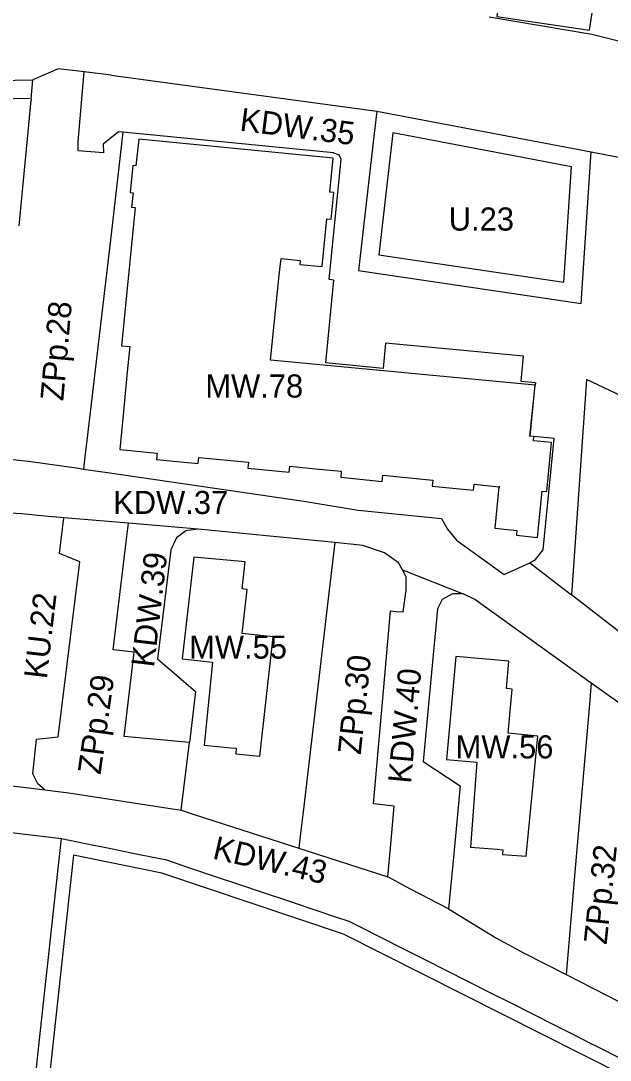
# Model space of a CAD drawing. Extents: x 7424434 to 7425898, y 5541432 to 5542659.
# Drawn here: x 7425392.8 to 7425520.4, y 5541625.5 to 5541850.5 of the extents above; entities that cross this region are included whole.
import ezdxf

# ---------------------------------------------------------------- set-up
doc = ezdxf.new("R2010")
doc.units = 0
for name, color, linetype in [('linie rozgraniczające', 7, 'Continuous'), ('nieprzekraczalne linie zabudowy', 7, 'Continuous'), ('obowiazujace linie zabudowy', 7, 'Continuous'), ('przeznaczenia terenów', 7, 'Continuous')]:
    doc.layers.add(name, color=color, linetype=linetype)

msp = doc.modelspace()

# ---------------------------------------------------------------- linework, layer by layer
at = {"layer": 'linie rozgraniczające'}
for p, q in [((7425516.46, 5541847.52), (7425494.23, 5541851.23)), ((7425522.8, 5541845.92), (7425516.46, 5541847.52)), ((7425345.98, 5541836.72), (7425395.46, 5541837.71)), ((7425395.07, 5541833.56), (7425395.46, 5541837.71)), ((7425405.25, 5541824.25), (7425406.57, 5541839.4)), ((7425412.43, 5541838.68), (7425406.57, 5541839.4)), ((7425412.43, 5541838.68), (7425469.86, 5541830.93)), ((7425394.55, 5541827.93), (7425395.05, 5541833.31)), ((7425395.07, 5541833.56), (7425395.05, 5541833.31)), ((7425469.86, 5541830.93), (7425469.3, 5541826.03)), ((7425392.52, 5541806.05), (7425394.55, 5541827.93)), ((7425413.98, 5541826.45), (7425410.7, 5541823.77)), ((7425414.93, 5541826.36), (7425412.37, 5541804.28)), ((7425414.93, 5541826.36), (7425413.98, 5541826.45)), ((7425460.55, 5541821.87), (7425414.93, 5541826.36)), ((7425469.3, 5541826.03), (7425465.91, 5541796.39)), ((7425405.25, 5541822.33), (7425405.25, 5541824.25)), ((7425410.7, 5541823.77), (7425410.72, 5541821.85)), ((7425410.72, 5541821.85), (7425405.25, 5541822.33)), ((7425460.55, 5541821.87), (7425461.74, 5541821.42)), ((7425462.17, 5541820.54), (7425461.74, 5541821.42)), ((7425514.1, 5541789.29), (7425516.28, 5541822.09)), ((7425459.55, 5541794.44), (7425462.17, 5541820.54)), ((7425412.37, 5541804.28), (7425406.96, 5541758.4)), ((7425460.6, 5541794.34), (7425459.55, 5541794.44)), ((7425465.91, 5541796.39), (7425514.1, 5541789.29)), ((7425458.83, 5541776.39), (7425460.6, 5541794.34)), ((7425471.8, 5541780.69), (7425471.28, 5541775.22)), ((7425501.67, 5541777.86), (7425471.8, 5541780.69)), ((7425501.15, 5541772.39), (7425501.67, 5541777.86)), ((7425471.28, 5541775.22), (7425458.83, 5541776.39)), ((7425504.2, 5541772.1), (7425501.15, 5541772.39)), ((7425504.2, 5541772.1), (7425504.16, 5541771.6)), ((7425515.3, 5541772.85), (7425512.02, 5541726.19)), ((7425528.15, 5541766.73), (7425515.3, 5541772.85)), ((7425503.03, 5541760.57), (7425504.16, 5541771.6)), ((7425503.86, 5541760.5), (7425503.03, 5541760.57)), ((7425508.27, 5541760.07), (7425503.86, 5541760.5)), ((7425505.9, 5541735.97), (7425508.27, 5541760.07)), ((7425406.7, 5541756.18), (7425406.38, 5541753.44)), ((7425406.96, 5541758.4), (7425406.7, 5541756.18)), ((7425385.12, 5541756.09), (7425394.51, 5541755.17)), ((7425394.51, 5541755.17), (7425405.3, 5541753.6)), ((7425405.3, 5541753.6), (7425406.38, 5541753.44)), ((7425406.38, 5541753.44), (7425411.59, 5541752.68)), ((7425411.59, 5541752.68), (7425454.13, 5541746.46)), ((7425454.13, 5541746.46), (7425455.86, 5541746.17)), ((7425455.86, 5541746.17), (7425465.85, 5541744.51)), ((7425393.08, 5541743.75), (7425383.22, 5541744.34)), ((7425398.02, 5541743.25), (7425393.08, 5541743.75)), ((7425402.12, 5541742.9), (7425398.02, 5541743.25)), ((7425401.2, 5541735.15), (7425402.12, 5541742.9)), ((7425416.15, 5541741.72), (7425402.12, 5541742.9)), ((7425465.85, 5541744.51), (7425483.92, 5541742.7)), ((7425483.92, 5541742.7), (7425485.22, 5541740.41)), ((7425415.73, 5541738.29), (7425416.15, 5541741.72)), ((7425431.23, 5541740.45), (7425416.15, 5541741.72)), ((7425431.23, 5541740.45), (7425428.57, 5541740.07)), ((7425460.83, 5541737.52), (7425431.23, 5541740.45)), ((7425412.81, 5541714.33), (7425415.73, 5541738.29)), ((7425426.51, 5541738.53), (7425425.31, 5541735.94)), ((7425428.57, 5541740.07), (7425426.51, 5541738.53)), ((7425485.22, 5541740.41), (7425487.12, 5541738.08)), ((7425425.31, 5541735.94), (7425422.87, 5541715.83)), ((7425460.83, 5541737.52), (7425459.61, 5541727.21)), ((7425466.87, 5541736.92), (7425460.83, 5541737.52)), ((7425471.57, 5541735.29), (7425466.87, 5541736.92)), ((7425487.12, 5541738.08), (7425497.43, 5541730.61)), ((7425504.24, 5541733.85), (7425505.9, 5541735.97)), ((7425405.59, 5541733.39), (7425401.2, 5541735.15)), ((7425474.6, 5541733.17), (7425471.57, 5541735.29)), ((7425503.03, 5541733.14), (7425504.24, 5541733.85)), ((7425400.94, 5541695.5), (7425405.59, 5541733.39)), ((7425475.44, 5541731.61), (7425474.6, 5541733.17)), ((7425475.44, 5541731.61), (7425488.61, 5541726.42)), ((7425476.25, 5541730.08), (7425475.44, 5541731.61)), ((7425497.43, 5541730.61), (7425503.03, 5541733.14)), ((7425503.03, 5541733.14), (7425512.02, 5541726.19)), ((7425476.24, 5541727.19), (7425476.25, 5541730.08)), ((7425459.61, 5541727.21), (7425453.93, 5541679.25)), ((7425475.58, 5541722.5), (7425476.24, 5541727.19)), ((7425484.03, 5541725.18), (7425483.04, 5541723.17)), ((7425486.3, 5541726.43), (7425484.03, 5541725.18)), ((7425488.61, 5541726.42), (7425486.3, 5541726.43)), ((7425491.07, 5541725.24), (7425488.61, 5541726.42)), ((7425516.3, 5541707.13), (7425491.07, 5541725.24)), ((7425538, 5541706.09), (7425512.02, 5541726.19)), ((7425471.62, 5541708.66), (7425472.87, 5541722.72)), ((7425472.87, 5541722.72), (7425474.05, 5541722.63)), ((7425474.05, 5541722.63), (7425475.58, 5541722.5)), ((7425483.04, 5541723.17), (7425481.52, 5541707.11)), ((7425422.87, 5541715.83), (7425422.45, 5541712.36)), ((7425417.36, 5541713.82), (7425412.81, 5541714.33)), ((7425415.2, 5541695.57), (7425417.36, 5541713.82)), ((7425422.45, 5541712.36), (7425430.68, 5541705.31)), ((7425469.15, 5541680.97), (7425471.62, 5541708.66)), ((7425481.52, 5541707.11), (7425479.92, 5541690.17)), ((7425516.3, 5541707.13), (7425515.84, 5541701.75)), ((7425526.02, 5541700.16), (7425516.3, 5541707.13)), ((7425430.68, 5541705.31), (7425429.34, 5541694.27)), ((7425515.84, 5541701.75), (7425512.76, 5541666.17)), ((7425396.25, 5541694.94), (7425400.94, 5541695.5)), ((7425429.34, 5541694.27), (7425415.2, 5541695.57)), ((7425395.45, 5541687.47), (7425396.25, 5541694.94)), ((7425427.55, 5541679.6), (7425429.34, 5541694.27)), ((7425479.92, 5541690.17), (7425487.94, 5541684.88)), ((7425396.49, 5541685.28), (7425395.45, 5541687.47)), ((7425387.93, 5541685.22), (7425398.02, 5541683.98)), ((7425398.02, 5541683.98), (7425396.49, 5541685.28)), ((7425487.94, 5541684.88), (7425486.56, 5541670.15)), ((7425398.02, 5541683.98), (7425403.25, 5541683.34)), ((7425403.25, 5541683.34), (7425427.55, 5541679.6)), ((7425473.65, 5541680.47), (7425469.15, 5541680.97)), ((7425472.89, 5541672.22), (7425473.65, 5541680.47)), ((7425427.55, 5541679.6), (7425430.38, 5541678.68)), ((7425430.38, 5541678.68), (7425452.99, 5541671.38)), ((7425453.93, 5541679.25), (7425453.44, 5541675.18)), ((7425386.67, 5541675.3), (7425401.64, 5541673.46)), ((7425400.93, 5541666.97), (7425401.64, 5541673.46)), ((7425401.64, 5541673.46), (7425406.45, 5541672.49)), ((7425453.44, 5541675.18), (7425452.99, 5541671.38)), ((7425406.45, 5541672.49), (7425412.33, 5541671.29)), ((7425412.33, 5541671.29), (7425418.2, 5541670.1)), ((7425452.99, 5541671.38), (7425472.24, 5541665.16)), ((7425472.24, 5541665.16), (7425472.89, 5541672.22)), ((7425418.2, 5541670.1), (7425424.08, 5541668.91)), ((7425424.08, 5541668.91), (7425424.13, 5541668.9)), ((7425424.13, 5541668.9), (7425429.38, 5541667.14)), ((7425486.56, 5541670.15), (7425485.44, 5541658.29)), ((7425400.07, 5541659.04), (7425400.93, 5541666.97)), ((7425429.38, 5541667.14), (7425434.68, 5541665.36)), ((7425434.68, 5541665.36), (7425439.97, 5541663.58)), ((7425477.19, 5541662.5), (7425472.24, 5541665.16)), ((7425512.76, 5541666.17), (7425510.85, 5541644.02)), ((7425439.97, 5541663.58), (7425445.26, 5541661.81)), ((7425445.26, 5541661.81), (7425450.56, 5541660.03)), ((7425485.44, 5541658.29), (7425477.19, 5541662.5)), ((7425450.56, 5541660.03), (7425455.85, 5541658.25)), ((7425399.21, 5541651.1), (7425400.07, 5541659.04)), ((7425455.85, 5541658.25), (7425461.15, 5541656.47)), ((7425485.44, 5541658.29), (7425495.8, 5541651.91)), ((7425461.15, 5541656.47), (7425463.81, 5541655.58)), ((7425463.81, 5541655.58), (7425466.15, 5541654.4)), ((7425466.15, 5541654.4), (7425470.85, 5541652.03)), ((7425398.77, 5541647.08), (7425399.21, 5541651.1)), ((7425470.85, 5541652.03), (7425475.55, 5541649.66)), ((7425495.8, 5541651.91), (7425501.61, 5541648.76)), ((7425475.55, 5541649.66), (7425480.25, 5541647.29)), ((7425501.61, 5541648.76), (7425510.85, 5541644.02)), ((7425398.34, 5541643.17), (7425398.77, 5541647.08)), ((7425480.25, 5541647.29), (7425484.95, 5541644.92)), ((7425484.95, 5541644.92), (7425489.65, 5541642.55)), ((7425510.85, 5541644.02), (7425527.38, 5541635.55)), ((7425397.48, 5541635.23), (7425398.34, 5541643.17)), ((7425489.65, 5541642.55), (7425494.35, 5541640.18)), ((7425494.35, 5541640.18), (7425499.05, 5541637.81)), ((7425499.05, 5541637.81), (7425503.75, 5541635.43)), ((7425396.61, 5541627.3), (7425397.48, 5541635.23)), ((7425503.75, 5541635.43), (7425508.45, 5541633.06)), ((7425508.45, 5541633.06), (7425513.15, 5541630.69)), ((7425513.15, 5541630.69), (7425515.65, 5541629.43)), ((7425515.65, 5541629.43), (7425517.85, 5541628.32)), ((7425517.85, 5541628.32), (7425522.55, 5541625.95)), ((7425396.09, 5541622.49), (7425396.61, 5541627.3))]:
    msp.add_line(p, q, dxfattribs=at)
for points in [[(7425406.57, 5541839.4), (7425400.89, 5541840.09), (7425395.46, 5541837.71)], [(7425469.86, 5541830.93), (7425516.28, 5541822.09), (7425524.07, 5541820.61)]]:
    msp.add_lwpolyline(points, dxfattribs=at)
at = {"layer": 'nieprzekraczalne linie zabudowy'}
msp.add_line((7425394.74, 5541833.62), (7425344.16, 5541832.69), dxfattribs=at)
msp.add_lwpolyline([(7425512.05, 5541818.83), (7425473.34, 5541826.19), (7425473.27, 5541825.58), (7425470.32, 5541799.78), (7425510.4, 5541793.88), (7425512.05, 5541818.83)], dxfattribs=at)
msp.add_lwpolyline([(7425516.21, 5541550.81), (7425539.76, 5541559.82), (7425542.87, 5541562.42), (7425566.11, 5541581.87), (7425568.69, 5541610.4), (7425544.11, 5541613.7), (7425524.39, 5541621.67), (7425514.3, 5541626.75), (7425462.65, 5541652.8), (7425423.35, 5541666), (7425404.27, 5541669.87), (7425401.75, 5541646.75), (7425399.07, 5541622.15), (7425398.91, 5541620.78), (7425392.88, 5541565.32), (7425432.43, 5541559.06), (7425432.38, 5541558.61), (7425444.12, 5541557.2), (7425463.89, 5541554.08), (7425469.74, 5541553.7)], close=True, dxfattribs=at)
at = {"layer": 'obowiazujace linie zabudowy'}
for points in [[(7425495.79, 5541863.41), (7425494.92, 5541857.32), (7425496.68, 5541857.06), (7425495.85, 5541851.41), (7425515.92, 5541848.41), (7425516.76, 5541854.06), (7425518.54, 5541853.79), (7425519.44, 5541859.88), (7425513.21, 5541860.83), (7425513.37, 5541861.98), (7425502.2, 5541863.69), (7425502.02, 5541862.51)], [(7425507.71, 5541759.15), (7425503.77, 5541759.54), (7425503.86, 5541760.5), (7425503.08, 5541760.57), (7425504.16, 5541771.6), (7425446.9, 5541777.02), (7425448.79, 5541795.43), (7425449.17, 5541799.02), (7425453.29, 5541798.61), (7425453.2, 5541797.72), (7425458.07, 5541797.24), (7425459.1, 5541807.62), (7425460.01, 5541807.53), (7425460.58, 5541813.3), (7425459.71, 5541813.39), (7425460.44, 5541820.72), (7425418.35, 5541824.87), (7425417.77, 5541819.09), (7425417.12, 5541819.15), (7425416.54, 5541813.27), (7425417.14, 5541813.21), (7425416.83, 5541810.13), (7425417.57, 5541810.06), (7425414.6, 5541780.11), (7425416.43, 5541779.93), (7425415.89, 5541774.45), (7425414.98, 5541765.11), (7425414.24, 5541757.68), (7425422.36, 5541756.88), (7425422.23, 5541755.53), (7425431.23, 5541754.64), (7425431.36, 5541755.97), (7425442.12, 5541754.91), (7425441.99, 5541753.62), (7425450.92, 5541752.74), (7425451.05, 5541754.06), (7425456.64, 5541753.51), (7425462.21, 5541752.96), (7425462.08, 5541751.66), (7425471.03, 5541750.77), (7425471.17, 5541752.1), (7425481.98, 5541751.03), (7425481.85, 5541749.74), (7425490.81, 5541748.85), (7425490.94, 5541750.13), (7425496.33, 5541749.6), (7425496.53, 5541749.58), (7425496.53, 5541749.57), (7425496.33, 5541749.6), (7425495.44, 5541740.61), (7425500.21, 5541740.14), (7425500.11, 5541739.11), (7425504.7, 5541738.65), (7425505.69, 5541748.68), (7425506.67, 5541748.58)], [(7425430.28, 5541734.37), (7425427.78, 5541712.38), (7425434.36, 5541711.64), (7425432.54, 5541693.71), (7425438.3, 5541693.12), (7425439.47, 5541693), (7425439.35, 5541691.82), (7425444.56, 5541691.29), (7425447.47, 5541717.09), (7425440.78, 5541717.84), (7425441.86, 5541727.35), (7425440.74, 5541727.48), (7425441.4, 5541733.33)], [(7425486.97, 5541712.84), (7425484.99, 5541690.59), (7425491.57, 5541690.01), (7425490.18, 5541671.58), (7425495.94, 5541671.15), (7425497.13, 5541671.06), (7425497.06, 5541670.05), (7425502.24, 5541669.66), (7425504.73, 5541695.64), (7425498.29, 5541696.26), (7425499.2, 5541705.8), (7425497.97, 5541705.92), (7425498.45, 5541711.85)]]:
    msp.add_lwpolyline(points, close=True, dxfattribs=at)

# ---------------------------------------------------------------- texts
at = {"layer": 'przeznaczenia terenów'}
for s, rotation, p in [('KDW.35', 352.6847, (7425440.08, 5541826.69)), ('ZPp.28', 85, (7425402.03, 5541768.07)), ('KDW.39', 83.3442, (7425421.67, 5541710.4)), ('KU.22', 83.4529, (7425398.47, 5541707.87)), ('ZPp.30', 84, (7425466.4, 5541691.49)), ('KDW.40', 84.7689, (7425477.27, 5541685.27)), ('ZPp.29', 82, (7425410.09, 5541687.17)), ('KDW.43', 347, (7425434.15, 5541669.17)), ('ZPp.32', 84, (7425519.63, 5541650.41))]:
    msp.add_text(s, height=5, rotation=rotation, dxfattribs=at).set_placement(p)
for s, p in [('U.23', (7425485.46, 5541805.05)), ('MW.78', (7425432.77, 5541768.91)), ('KDW.37', (7425412.83, 5541743.71)), ('MW.55', (7425429.27, 5541712.41)), ('MW.56', (7425486.94, 5541690.81))]:
    msp.add_text(s, height=5, dxfattribs=at).set_placement(p)

doc.saveas('drawing.dxf')
